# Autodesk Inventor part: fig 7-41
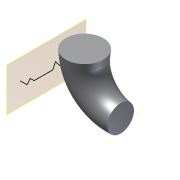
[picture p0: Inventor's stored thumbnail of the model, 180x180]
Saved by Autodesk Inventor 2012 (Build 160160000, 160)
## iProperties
Created: 2011-07
Part Number: fig 7-41
Material: Default
Document SubType Name: Modeling
Designer: CadCim
Density: 1 g/cm^3
Author: CadCim
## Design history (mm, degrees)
sketch "Sketch1"
  geometry: 1 further point
sketch "Sketch2"
  geometry: L1 (9, 5.1)-(9, 4.1); L2 (2.9, -2)-(2.9, -2); A1 r 6.1 centre (2.9, 4.1) between (2.9, -2) and (9, 4.1); 1 further point
  constraints: 4 end point, 2 point on circle, 2 tangent, 1 centre point, 1 perpendicular, 1 vertical
workplane "Work Plane1"
sketch "Sketch3"
  geometry: C1 r 2.236 at (0, 0); 1 further point
  constraints: 1 centre point
sweep "Sweep1" sketch "Sketch3" dims "d0" = 5 deg
workplane "Work Plane3"
sketch "Sketch5"
  geometry: L1 (5, -1)-(4, -1); L2 (4, -1)-(3, 0); L3 (3, 0)-(2.774, -1); L4 (2.774, -1)-(2, 0); L5 (2, 0)-(1.572, -1); L6 (1.572, -1)-(0.798, 0); L7 (0.798, 0)-(0.37, -1); L8 (0.37, -1)-(-2.804, -1); L9 (-2.804, -1)-(-3.466, -0.337); L10 (-3.466, -0.337)-(-4, -1); L11 (-4, -1)-(-5.153, 0.153); 1 further point
  constraints: 22 end point, 4 parallel, 1 collinear, 1 horizontal
body "Solid1"
other parameters: "d1" = -14.75
